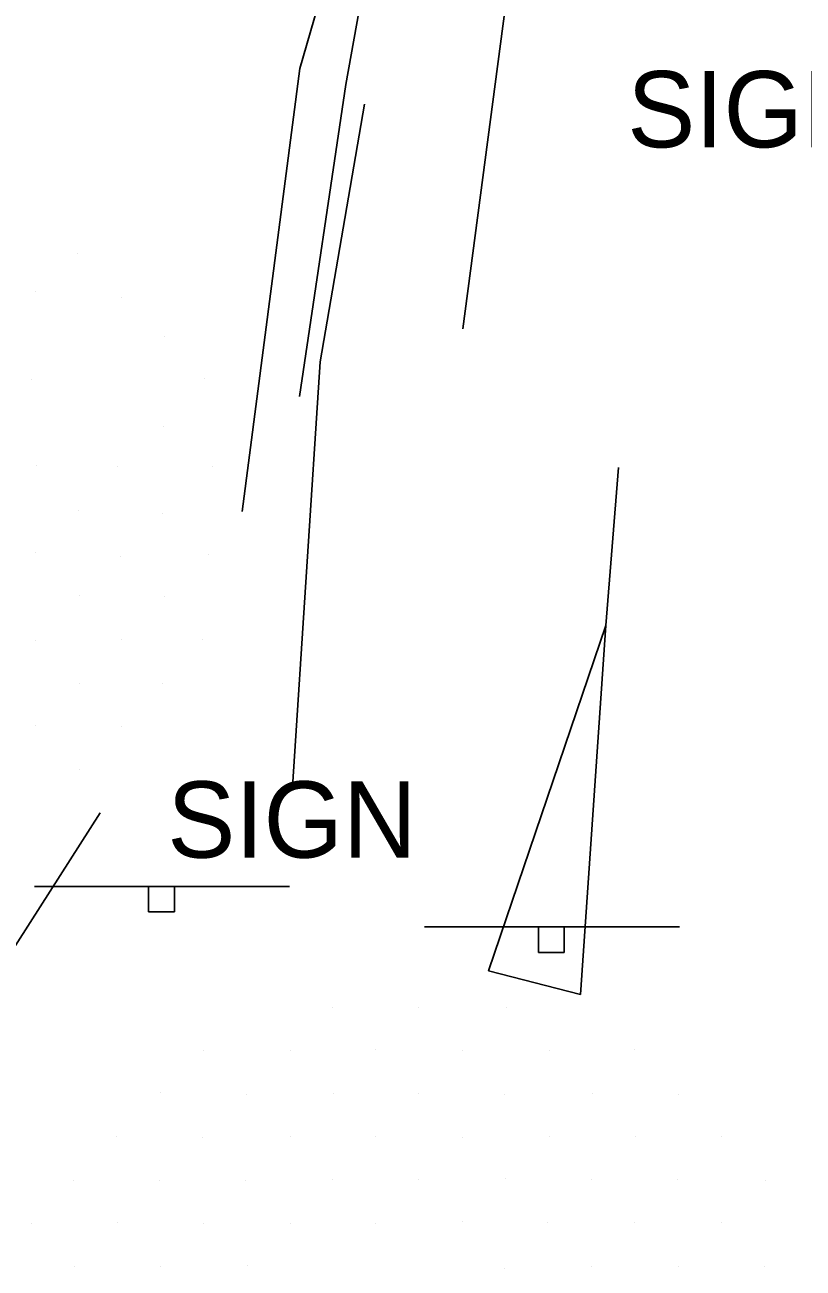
# Model space of a CAD drawing. Extents: x 1602514 to 1609837, y 863887 to 871157.
# Drawn here: x 1604814.6 to 1604878.4, y 866954.3 to 867056.2 of the extents above; entities that cross this region are included whole.
import ezdxf

# ---------------------------------------------------------------- set-up
doc = ezdxf.new("R2010")
doc.units = 0
for name, color, linetype in [('Roadway-Signs', 7, 'Continuous'), ('Survey-Centerline', 7, 'Continuous'), ('Survey-Edge of pavement', 7, 'Continuous'), ('Survey-Flow line', 7, 'Continuous'), ('Survey-Ridge Lines', 7, 'Continuous'), ('Survey-Safety', 7, 'Continuous'), ('Survey-Shoulders', 7, 'Continuous'), ('Survey-Spot dirt', 7, 'Continuous')]:
    doc.layers.add(name, color=color, linetype=linetype)

msp = doc.modelspace()

# ---------------------------------------------------------------- linework, layer by layer
at = {"layer": 'Roadway-Signs'}
for p, q in [((1604815.38, 866985.61), (1604836.29, 866985.61)), ((1604815.38, 866985.61), (1604836.29, 866985.61)), ((1604824.73, 866983.51), (1604824.73, 866985.61)), ((1604824.73, 866983.51), (1604824.73, 866985.61)), ((1604825.78, 866985.61), (1604825.78, 866985.61)), ((1604825.78, 866985.61), (1604825.78, 866985.61)), ((1604826.84, 866985.61), (1604826.84, 866983.51)), ((1604826.84, 866985.61), (1604826.84, 866983.51)), ((1604826.84, 866983.51), (1604824.73, 866983.51)), ((1604826.84, 866983.51), (1604824.73, 866983.51)), ((1604847.34, 866982.3), (1604868.24, 866982.3)), ((1604847.34, 866982.3), (1604868.24, 866982.3)), ((1604856.69, 866980.2), (1604856.69, 866982.3)), ((1604856.69, 866980.2), (1604856.69, 866982.3)), ((1604857.74, 866982.3), (1604857.74, 866982.3)), ((1604857.74, 866982.3), (1604857.74, 866982.3)), ((1604858.79, 866982.3), (1604858.79, 866980.2)), ((1604858.79, 866982.3), (1604858.79, 866980.2)), ((1604858.79, 866980.2), (1604856.69, 866980.2)), ((1604858.79, 866980.2), (1604856.69, 866980.2))]:
    msp.add_line(p, q, dxfattribs=at)
at = {"layer": 'Survey-Centerline'}
msp.add_lwpolyline([(1604863.25, 867019.92), (1604862.22, 867006.98), (1604860.13, 866976.76), (1604852.6, 866978.7), (1604862.22, 867006.98)], dxfattribs=at)
msp.add_lwpolyline([(1604863.25, 867019.92), (1604862.22, 867006.98), (1604860.13, 866976.76), (1604852.6, 866978.7), (1604862.22, 867006.98)], dxfattribs=at)
at = {"layer": 'Survey-Edge of pavement'}
msp.add_lwpolyline([(1604861.7, 867106.64), (1604856.22, 867074.72), (1604850.49, 867031.3)], dxfattribs=at)
msp.add_lwpolyline([(1604861.7, 867106.64), (1604856.22, 867074.72), (1604850.49, 867031.3)], dxfattribs=at)
at = {"layer": 'Survey-Flow line'}
msp.add_lwpolyline([(1604765.82, 866962.11), (1604784.7, 866964.49), (1604809.07, 866973.35), (1604820.76, 866991.64)], dxfattribs=at)
msp.add_lwpolyline([(1604765.82, 866962.11), (1604784.7, 866964.49), (1604809.07, 866973.35), (1604820.76, 866991.64)], dxfattribs=at)
at = {"layer": 'Survey-Ridge Lines'}
msp.add_lwpolyline([(1604867.32, 867150.71), (1604858.73, 867126.89), (1604850.4, 867102.2), (1604844.23, 867077.16), (1604837.12, 867052.62), (1604832.39, 867016.31)], dxfattribs=at)
msp.add_lwpolyline([(1604867.32, 867150.71), (1604858.73, 867126.89), (1604850.4, 867102.2), (1604844.23, 867077.16), (1604837.12, 867052.62), (1604832.39, 867016.31)], dxfattribs=at)
at = {"layer": 'Survey-Safety'}
msp.add_lwpolyline([(1604837.1, 867025.75), (1604840.9, 867051.3), (1604845.45, 867076.72), (1604851.39, 867101.82), (1604860.1, 867126.34), (1604869.46, 867149.82)], dxfattribs=at)
msp.add_lwpolyline([(1604837.1, 867025.75), (1604840.9, 867051.3), (1604845.45, 867076.72), (1604851.39, 867101.82), (1604860.1, 867126.34), (1604869.46, 867149.82)], dxfattribs=at)
at = {"layer": 'Survey-Shoulders'}
msp.add_lwpolyline([(1604842.42, 867049.69), (1604838.8, 867028.58), (1604836.54, 866994.17)], dxfattribs=at)
msp.add_lwpolyline([(1604842.42, 867049.69), (1604838.8, 867028.58), (1604836.54, 866994.17)], dxfattribs=at)
at = {"layer": 'Survey-Spot dirt'}
for p, q in [((1604818.94, 867037.5), (1604818.94, 867037.5)), ((1604818.94, 867037.5), (1604818.94, 867037.5)), ((1604815.45, 867034.34), (1604815.45, 867034.34)), ((1604815.45, 867034.34), (1604815.45, 867034.34)), ((1604822.53, 867033.87), (1604822.53, 867033.87)), ((1604822.53, 867033.87), (1604822.53, 867033.87)), ((1604826.05, 867030.67), (1604826.05, 867030.67)), ((1604826.05, 867030.67), (1604826.05, 867030.67)), ((1604815.15, 867027.11), (1604815.15, 867027.11)), ((1604815.15, 867027.11), (1604815.15, 867027.11)), ((1604829.31, 867027.2), (1604829.31, 867027.2)), ((1604829.31, 867027.2), (1604829.31, 867027.2)), ((1604825.99, 867023.27), (1604825.99, 867023.27)), ((1604825.99, 867023.27), (1604825.99, 867023.27)), ((1604815.55, 867020.08), (1604815.55, 867020.08)), ((1604815.55, 867020.08), (1604815.55, 867020.08)), ((1604822.22, 867020.03), (1604822.22, 867020.03)), ((1604822.22, 867020.03), (1604822.22, 867020.03)), ((1604829.94, 867019.97), (1604829.94, 867019.97)), ((1604829.94, 867019.97), (1604829.94, 867019.97)), ((1604819.01, 867016.38), (1604819.01, 867016.38)), ((1604819.01, 867016.38), (1604819.01, 867016.38)), ((1604825.91, 867016.17), (1604825.91, 867016.17)), ((1604825.91, 867016.17), (1604825.91, 867016.17)), ((1604815.45, 867012.93), (1604815.45, 867012.93)), ((1604815.45, 867012.93), (1604815.45, 867012.93)), ((1604822.45, 867012.62), (1604822.45, 867012.62)), ((1604822.45, 867012.62), (1604822.45, 867012.62)), ((1604829.62, 867012.83), (1604829.62, 867012.83)), ((1604829.62, 867012.83), (1604829.62, 867012.83)), ((1604819.04, 867009.41), (1604819.04, 867009.41)), ((1604819.04, 867009.41), (1604819.04, 867009.41)), ((1604826.07, 867009.34), (1604826.07, 867009.34)), ((1604826.07, 867009.34), (1604826.07, 867009.34)), ((1604815.49, 867005.74), (1604815.49, 867005.74)), ((1604815.49, 867005.74), (1604815.49, 867005.74)), ((1604822.5, 867005.87), (1604822.5, 867005.87)), ((1604822.5, 867005.87), (1604822.5, 867005.87)), ((1604829.14, 867005.84), (1604829.14, 867005.84)), ((1604829.14, 867005.84), (1604829.14, 867005.84)), ((1604819.07, 867002.21), (1604819.07, 867002.21)), ((1604819.07, 867002.21), (1604819.07, 867002.21)), ((1604825.88, 867002.21), (1604825.88, 867002.21)), ((1604825.88, 867002.21), (1604825.88, 867002.21)), ((1604815.44, 866998.75), (1604815.44, 866998.75)), ((1604815.44, 866998.75), (1604815.44, 866998.75)), ((1604822.51, 866998.68), (1604822.51, 866998.68)), ((1604822.51, 866998.68), (1604822.51, 866998.68)), ((1604819.04, 866995.19), (1604819.04, 866995.19)), ((1604819.04, 866995.19), (1604819.04, 866995.19)), ((1604839.78, 866975.69), (1604839.78, 866975.69)), ((1604839.78, 866975.69), (1604839.78, 866975.69)), ((1604846.89, 866975.69), (1604846.89, 866975.69)), ((1604846.89, 866975.69), (1604846.89, 866975.69)), ((1604854.04, 866975.67), (1604854.04, 866975.67)), ((1604854.04, 866975.67), (1604854.04, 866975.67)), ((1604829.24, 866972.19), (1604829.24, 866972.19)), ((1604829.24, 866972.19), (1604829.24, 866972.19)), ((1604836.32, 866972.18), (1604836.32, 866972.18)), ((1604836.32, 866972.18), (1604836.32, 866972.18)), ((1604843.35, 866972.23), (1604843.35, 866972.23)), ((1604843.35, 866972.23), (1604843.35, 866972.23)), ((1604850.49, 866972.12), (1604850.49, 866972.12)), ((1604850.49, 866972.12), (1604850.49, 866972.12)), ((1604857.56, 866972.12), (1604857.56, 866972.12)), ((1604857.56, 866972.12), (1604857.56, 866972.12)), ((1604864.57, 866972.21), (1604864.57, 866972.21)), ((1604864.57, 866972.21), (1604864.57, 866972.21)), ((1604825.67, 866968.73), (1604825.67, 866968.73)), ((1604825.67, 866968.73), (1604825.67, 866968.73)), ((1604832.76, 866968.56), (1604832.76, 866968.56)), ((1604832.76, 866968.56), (1604832.76, 866968.56)), ((1604839.85, 866968.62), (1604839.85, 866968.62)), ((1604839.85, 866968.62), (1604839.85, 866968.62)), ((1604846.82, 866968.67), (1604846.82, 866968.67)), ((1604846.82, 866968.67), (1604846.82, 866968.67)), ((1604853.94, 866968.53), (1604853.94, 866968.53)), ((1604853.94, 866968.53), (1604853.94, 866968.53)), ((1604861.1, 866968.63), (1604861.1, 866968.63)), ((1604861.1, 866968.63), (1604861.1, 866968.63)), ((1604868.14, 866968.56), (1604868.14, 866968.56)), ((1604868.14, 866968.56), (1604868.14, 866968.56)), ((1604822.09, 866965.1), (1604822.09, 866965.1)), ((1604822.09, 866965.1), (1604822.09, 866965.1)), ((1604829.18, 866965.07), (1604829.18, 866965.07)), ((1604829.18, 866965.07), (1604829.18, 866965.07)), ((1604836.34, 866965.1), (1604836.34, 866965.1)), ((1604836.34, 866965.1), (1604836.34, 866965.1)), ((1604843.34, 866965.13), (1604843.34, 866965.13)), ((1604843.34, 866965.13), (1604843.34, 866965.13)), ((1604850.46, 866965.07), (1604850.46, 866965.07)), ((1604850.46, 866965.07), (1604850.46, 866965.07)), ((1604857.62, 866965.15), (1604857.62, 866965.15)), ((1604857.62, 866965.15), (1604857.62, 866965.15)), ((1604864.63, 866965.13), (1604864.63, 866965.13)), ((1604864.63, 866965.13), (1604864.63, 866965.13)), ((1604871.65, 866965.1), (1604871.65, 866965.1)), ((1604871.65, 866965.1), (1604871.65, 866965.1)), ((1604818.56, 866961.55), (1604818.56, 866961.55)), ((1604818.56, 866961.55), (1604818.56, 866961.55)), ((1604825.65, 866961.5), (1604825.65, 866961.5)), ((1604825.65, 866961.5), (1604825.65, 866961.5)), ((1604832.71, 866961.55), (1604832.71, 866961.55)), ((1604832.71, 866961.55), (1604832.71, 866961.55)), ((1604839.82, 866961.58), (1604839.82, 866961.58)), ((1604839.82, 866961.58), (1604839.82, 866961.58)), ((1604846.82, 866961.63), (1604846.82, 866961.63)), ((1604846.82, 866961.63), (1604846.82, 866961.63)), ((1604854, 866961.68), (1604854, 866961.68)), ((1604854, 866961.68), (1604854, 866961.68)), ((1604861.04, 866961.61), (1604861.04, 866961.61)), ((1604861.04, 866961.61), (1604861.04, 866961.61)), ((1604868.12, 866961.58), (1604868.12, 866961.58)), ((1604868.12, 866961.58), (1604868.12, 866961.58)), ((1604875.28, 866961.53), (1604875.28, 866961.53)), ((1604875.28, 866961.53), (1604875.28, 866961.53)), ((1604815.12, 866958), (1604815.12, 866958)), ((1604815.12, 866958), (1604815.12, 866958)), ((1604822.17, 866958.06), (1604822.17, 866958.06)), ((1604822.17, 866958.06), (1604822.17, 866958.06)), ((1604829.24, 866957.95), (1604829.24, 866957.95)), ((1604829.24, 866957.95), (1604829.24, 866957.95)), ((1604836.34, 866958), (1604836.34, 866958)), ((1604836.34, 866958), (1604836.34, 866958)), ((1604843.32, 866958.02), (1604843.32, 866958.02)), ((1604843.32, 866958.02), (1604843.32, 866958.02)), ((1604850.43, 866958.11), (1604850.43, 866958.11)), ((1604850.43, 866958.11), (1604850.43, 866958.11)), ((1604857.46, 866958.05), (1604857.46, 866958.05)), ((1604857.46, 866958.05), (1604857.46, 866958.05)), ((1604864.55, 866958.08), (1604864.55, 866958.08)), ((1604864.55, 866958.08), (1604864.55, 866958.08)), ((1604871.67, 866958.05), (1604871.67, 866958.05)), ((1604871.67, 866958.05), (1604871.67, 866958.05)), ((1604818.68, 866954.49), (1604818.68, 866954.49)), ((1604818.68, 866954.49), (1604818.68, 866954.49)), ((1604825.69, 866954.45), (1604825.69, 866954.45)), ((1604825.69, 866954.45), (1604825.69, 866954.45)), ((1604832.81, 866954.52), (1604832.81, 866954.52)), ((1604832.81, 866954.52), (1604832.81, 866954.52)), ((1604853.93, 866954.33), (1604853.93, 866954.33)), ((1604853.93, 866954.33), (1604853.93, 866954.33)), ((1604861.05, 866954.44), (1604861.05, 866954.44)), ((1604861.05, 866954.44), (1604861.05, 866954.44)), ((1604868.13, 866954.5), (1604868.13, 866954.5)), ((1604868.13, 866954.5), (1604868.13, 866954.5)), ((1604875.21, 866954.43), (1604875.21, 866954.43)), ((1604875.21, 866954.43), (1604875.21, 866954.43))]:
    msp.add_line(p, q, dxfattribs=at)

# ---------------------------------------------------------------- texts
at = {"layer": 'Roadway-Signs'}
for p in [(1604863.96, 867046.16), (1604863.96, 867046.16), (1604826.26, 866987.96), (1604826.26, 866987.96)]:
    msp.add_text('SIGN', height=6.25, dxfattribs=at).set_placement(p)

doc.saveas('drawing.dxf')
